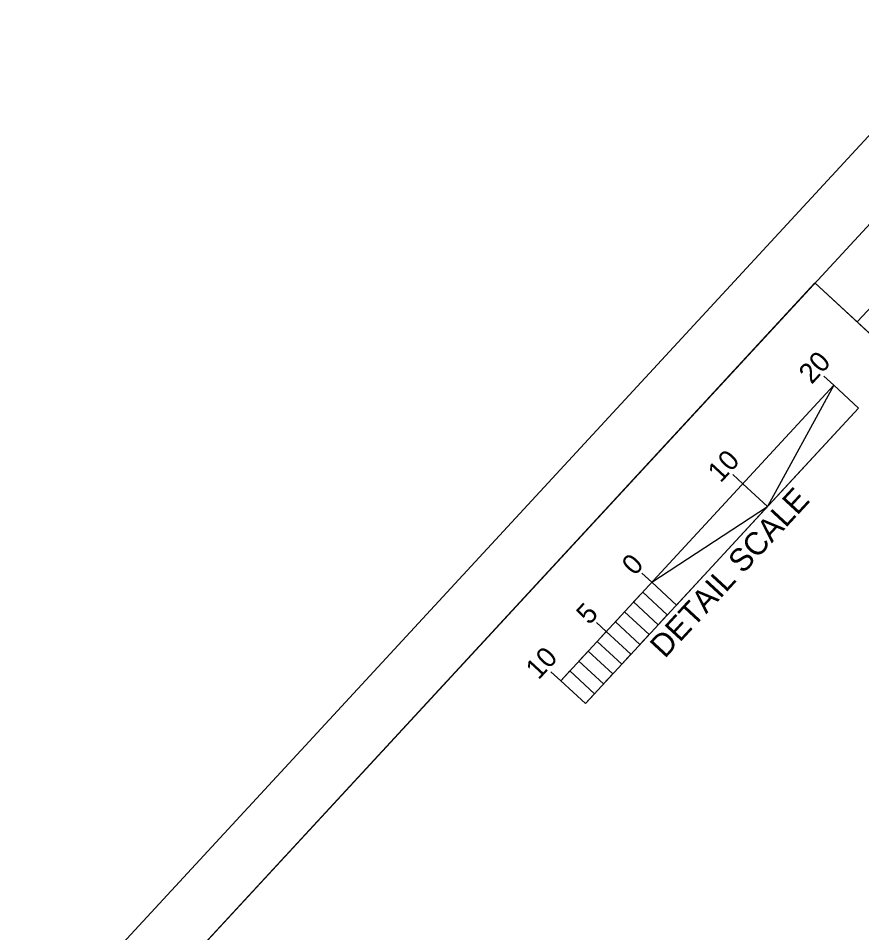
# Model space of a CAD drawing. Extents: x 1768274 to 1769121, y 999922 to 1000687.
# Drawn here: x 1768888.3 to 1768951.2, y 1000252.8 to 1000321 of the extents above; entities that cross this region are included whole.
import ezdxf

# ---------------------------------------------------------------- set-up
doc = ezdxf.new("R2010")
doc.units = 0
for name, color, linetype in [('E_NCDOT_Terrain_Model_Contour_Imported', 7, 'Continuous'), ('E_NCDOT_Terrain_Model_Contour_Major', 7, 'Continuous'), ('E_NCDOT_Terrain_Model_Hole', 7, 'Continuous'), ('E_NCDOT_Terrain_Model_Spot_Elevation', 7, 'Continuous'), ('E_NCDOT_Terrain_Model_Triangles', 7, 'Continuous')]:
    doc.layers.add(name, color=color, linetype=linetype)

msp = doc.modelspace()

# ---------------------------------------------------------------- linework, layer by layer
at = {"layer": 'E_NCDOT_Terrain_Model_Contour_Imported'}
msp.add_lwpolyline([(1768737.288, 1000073.608), (1768947.711, 1000301.251), (1769102.655, 1000158.029), (1768892.232, 999930.385)], close=True, dxfattribs=at)
at = {"layer": 'E_NCDOT_Terrain_Model_Contour_Major'}
for p, q in [((1768961.29, 1000315.942), (1768737.288, 1000073.608)), ((1768964.436, 1000313.034), (1768950.86, 1000298.347)), ((1769102.655, 1000158.029), (1768947.714, 1000301.255))]:
    msp.add_line(p, q, dxfattribs=at)
at = {"layer": 'E_NCDOT_Terrain_Model_Hole'}
for p, q in [((1768949.119, 1000293.629), (1768948.384, 1000294.308)), ((1768949.119, 1000293.629), (1768928.755, 1000271.599)), ((1768950.956, 1000291.93), (1768949.119, 1000293.629)), ((1768930.591, 1000269.902), (1768950.956, 1000291.93)), ((1768942.331, 1000286.285), (1768941.598, 1000286.962)), ((1768942.331, 1000286.285), (1768944.167, 1000284.588)), ((1768935.545, 1000278.94), (1768934.81, 1000279.619)), ((1768933.507, 1000276.739), (1768935.342, 1000275.042)), ((1768932.151, 1000275.269), (1768931.415, 1000275.949)), ((1768928.755, 1000271.599), (1768928.023, 1000272.276)), ((1768928.023, 1000272.276), (1768928.023, 1000272.276)), ((1768928.755, 1000271.599), (1768930.591, 1000269.902)), ((1768928.755, 1000271.599), (1768928.755, 1000271.599))]:
    msp.add_line(p, q, dxfattribs=at)
for points in [[(1768949.119, 1000293.629), (1768944.167, 1000284.588), (1768950.956, 1000291.93)], [(1768935.545, 1000278.94), (1768944.167, 1000284.588), (1768937.381, 1000277.243)], [(1768934.185, 1000277.473), (1768934.864, 1000278.208), (1768936.702, 1000276.509), (1768936.021, 1000275.776)], [(1768932.83, 1000276.003), (1768933.507, 1000276.739), (1768935.342, 1000275.042), (1768934.664, 1000274.308)], [(1768931.472, 1000274.534), (1768932.151, 1000275.269), (1768933.985, 1000273.573), (1768933.306, 1000272.839)], [(1768930.113, 1000273.067), (1768930.793, 1000273.8), (1768932.629, 1000272.103), (1768931.952, 1000271.37)], [(1768928.755, 1000271.599), (1768929.434, 1000272.333), (1768931.27, 1000270.636), (1768930.591, 1000269.902)]]:
    msp.add_lwpolyline(points, close=True, dxfattribs=at)
at = {"layer": 'E_NCDOT_Terrain_Model_Spot_Elevation'}
msp.add_lwpolyline([(1768729.032, 1000071.305), (1768959.819, 1000320.98), (1769121.372, 1000171.648), (1768890.585, 999921.973)], close=True, dxfattribs=at)

# ---------------------------------------------------------------- texts
at = {"layer": 'E_NCDOT_Terrain_Model_Hole'}
for s, height, p in [('DETAIL SCALE', 1.69992, (1768936.511, 1000273.209)), ('0', 1.5, (1768934.268, 1000279.371))]:
    msp.add_text(s, height=height, rotation=47.25123, dxfattribs=at).set_placement(p)
at = {"layer": 'E_NCDOT_Terrain_Model_Triangles'}
for s, p in [('20', (1768947.461, 1000293.643)), ('10', (1768940.673, 1000286.3)), ('5', (1768930.881, 1000275.706)), ('10', (1768927.097, 1000271.613))]:
    msp.add_text(s, height=1.5, rotation=47.25123, dxfattribs=at).set_placement(p)

doc.saveas('drawing.dxf')
